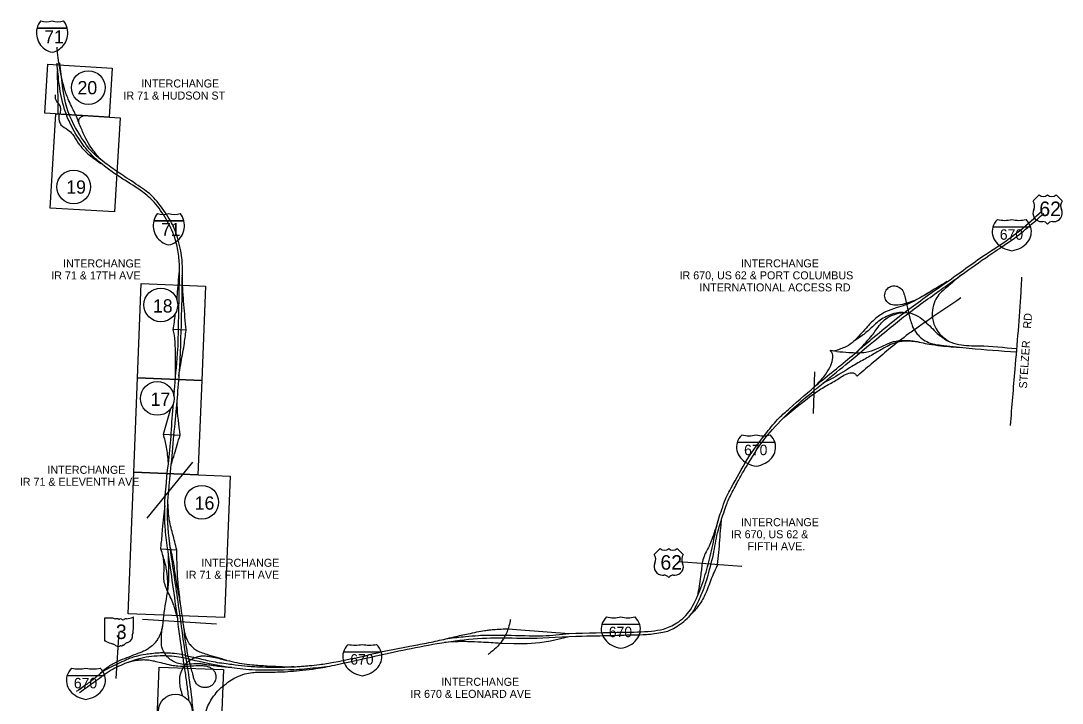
# Model space of a CAD drawing. Extents: x -13 to 322, y -402 to 112.
# Drawn here: x 3.88 to 16.74, y 73.08 to 81.51 of the extents above; entities that cross this region are included whole.
import ezdxf

# ---------------------------------------------------------------- set-up
doc = ezdxf.new("R2010")
doc.units = 0
for name, color, linetype in [('Default', 7, 'Continuous'), ('GM_X_Interstate_Shield', 7, 'Continuous'), ('GM_X_State_Shield', 7, 'Continuous'), ('GM_X_US_Shield', 7, 'Continuous'), ('SC_Scratch1', 7, 'Continuous'), ('SH_Data', 7, 'Continuous'), ('SH_Text', 7, 'Continuous')]:
    doc.layers.add(name, color=color, linetype=linetype)

# ---------------------------------------------------------------- blocks, each defined once
blk = doc.blocks.new('FENCE')
at = {"layer": 'Default'}
blk.add_lwpolyline([(-54.6, 79.5), (232.4, 79.5), (232.4, -116), (-54.6, -116)], close=True, dxfattribs=at)

msp = doc.modelspace()

# ---------------------------------------------------------------- linework, layer by layer
at = {"layer": 'GM_X_Interstate_Shield'}
for p, q in [((4.078, 81.42), (4.45, 81.42)), ((4.45, 81.42), (4.078, 81.42)), ((4.45, 81.42), (4.078, 81.42)), ((5.519, 79.04), (5.891, 79.04)), ((5.891, 79.04), (5.519, 79.04)), ((5.891, 79.04), (5.519, 79.04)), ((16.35, 78.962), (15.882, 78.962)), ((16.35, 78.962), (15.882, 78.962)), ((13.192, 76.302), (12.725, 76.302)), ((13.192, 76.302), (12.725, 76.302)), ((11.521, 74.055), (11.053, 74.055)), ((11.521, 74.055), (11.053, 74.055)), ((8.329, 73.716), (7.861, 73.716)), ((8.329, 73.716), (7.861, 73.716)), ((4.915, 73.423), (4.448, 73.423)), ((4.915, 73.423), (4.448, 73.423))]:
    msp.add_line(p, q, dxfattribs=at)
for centre, start, end in [((4.313, 81.36), 165.8066, 258.463), ((4.313, 81.36), 141.669, 165.8066), ((4.194, 81.741), 253.0091, 286.9909), ((4.335, 81.741), 253.0091, 286.9909), ((4.216, 81.36), 281.537, 14.1934), ((4.216, 81.36), 14.1934, 38.331), ((5.754, 78.981), 141.669, 165.8066), ((5.635, 79.362), 253.0091, 286.9909), ((5.776, 79.362), 253.0091, 286.9909), ((5.657, 78.981), 14.1934, 38.331), ((5.754, 78.981), 165.8066, 258.463), ((5.657, 78.981), 281.537, 14.1934)]:
    msp.add_arc(centre, 0.242, start, end, dxfattribs=at)
for centre, start_param, end_param in [((16.176, 78.907), 2.911027, 4.511031), ((16.176, 78.907), 2.47259, 2.911027), ((16.028, 79.288), 4.415841, 5.008937), ((16.204, 79.288), 4.415841, 5.008937), ((16.056, 78.907), 4.913747, 6.513751), ((16.056, 78.907), 0.230566, 0.669003), ((13.019, 76.246), 2.47259, 2.911027), ((12.87, 76.628), 4.415841, 5.008937), ((13.047, 76.628), 4.415841, 5.008937), ((12.898, 76.246), 0.230566, 0.669003), ((13.019, 76.246), 2.911027, 4.511031), ((12.898, 76.246), 4.913747, 6.513751), ((11.348, 74), 2.47259, 2.911027), ((11.199, 74.381), 4.415841, 5.008937), ((11.375, 74.381), 4.415841, 5.008937), ((11.227, 74), 0.230566, 0.669003), ((11.348, 74), 2.911027, 4.511031), ((11.227, 74), 4.913747, 6.513751), ((8.156, 73.66), 2.911027, 4.511031), ((8.156, 73.66), 2.47259, 2.911027), ((8.007, 74.042), 4.415841, 5.008937), ((8.183, 74.042), 4.415841, 5.008937), ((8.035, 73.66), 4.913747, 6.513751), ((8.035, 73.66), 0.230566, 0.669003), ((4.742, 73.368), 2.47259, 2.911027), ((4.593, 73.749), 4.415841, 5.008937), ((4.77, 73.749), 4.415841, 5.008937), ((4.621, 73.368), 0.230566, 0.669003), ((4.742, 73.368), 2.911027, 4.511031), ((4.621, 73.368), 4.913747, 6.513751)]:
    msp.add_ellipse(centre, major_axis=(0.302, 0), ratio=0.8, start_param=start_param, end_param=end_param, dxfattribs=at)
at = {"layer": 'GM_X_State_Shield'}
for p, q in [((4.911, 74.13), (4.911, 73.858)), ((5.02, 74.135), (4.915, 74.135)), ((5.27, 73.999), (5.27, 74.142)), ((5.27, 73.999), (5.27, 73.999))]:
    msp.add_line(p, q, dxfattribs=at)
for centre, radius, start, end in [((4.916, 74.131), 0.00416, 98.1301, 188.1301), ((5.045, 74.167), 0.0403, 231.6195, 271.1119), ((5.058, 73.982), 0.145, 80.4867, 94.9883), ((5.091, 74.132), 0.0116, 219.7921, 297.1024), ((5.108, 74.101), 0.0242, 54.4667, 119.1411), ((5.14, 74.144), 0.0291, 233.8562, 294.8282), ((5.191, 74.052), 0.0766, 97.3462, 120.7689), ((5.143, 74.506), 0.381, 275.8445, 288.9065), ((5.266, 74.142), 0.004, 351.8621, 97.738), ((5.285, 73.94), 0.027, 136.8065, 186.9296), ((5.269, 73.989), 0.00618, 107.944, 210.337), ((5.23, 73.971), 0.0371, 340.033, 23.6496), ((5.266, 73.999), 0.00428, 289.6038, 7.7341), ((4.916, 73.857), 0.0042, 171.9584, 258.3066), ((4.916, 73.885), 0.032, 267.339, 280.6039), ((4.923, 73.842), 0.0115, 29.7484, 93.2717), ((5.069, 74.087), 0.275, 240.4129, 257.1985), ((4.987, 73.735), 0.086, 47.1842, 75.836), ((5.204, 73.781), 0.0521, 94.4031, 142.5768), ((5.164, 73.921), 0.0952, 292.3089, 8.9858), ((5.08, 73.841), 0.0546, 230.7004, 286.2918), ((5.111, 73.747), 0.0448, 85.6951, 111.2099), ((5.115, 73.82), 0.0291, 268.777, 315.5493), ((5.141, 73.794), 0.00819, 65.7517, 132.6484), ((5.138, 73.831), 0.0308, 282.8732, 323.2771)]:
    msp.add_arc(centre, radius, start, end, dxfattribs=at)
at = {"layer": 'GM_X_US_Shield'}
for p, q in [((16.453, 79.36), (16.378, 79.286)), ((16.737, 79.286), (16.662, 79.36)), ((16.483, 79.031), (16.498, 79.031)), ((16.617, 79.031), (16.632, 79.031)), ((11.774, 74.994), (11.699, 74.92)), ((12.058, 74.92), (11.984, 74.994)), ((11.804, 74.665), (11.819, 74.665)), ((11.939, 74.665), (11.954, 74.665))]:
    msp.add_line(p, q, dxfattribs=at)
for centre, radius, start, end in [((16.505, 79.414), 0.0748, 225.573, 314.427), ((16.61, 79.414), 0.0748, 225.573, 314.427), ((16.292, 79.225), 0.105, 334.5471, 35.0009), ((16.823, 79.225), 0.105, 144.9991, 205.4529), ((16.482, 79.136), 0.105, 154.8319, 270.6383), ((16.634, 79.136), 0.105, 269.3617, 25.1681), ((16.498, 78.956), 0.0748, 36.8699, 90), ((16.617, 78.956), 0.0748, 90, 143.1301), ((11.827, 75.048), 0.0748, 225.573, 314.427), ((11.931, 75.048), 0.0748, 225.573, 314.427), ((11.614, 74.86), 0.105, 334.5471, 35.0009), ((12.144, 74.86), 0.105, 144.9991, 205.4529), ((11.803, 74.77), 0.105, 154.8319, 270.6383), ((11.955, 74.77), 0.105, 269.3617, 25.1681), ((11.819, 74.591), 0.0748, 36.8699, 90), ((11.939, 74.591), 0.0748, 90, 143.1301)]:
    msp.add_arc(centre, radius, start, end, dxfattribs=at)
at = {"layer": 'SC_Scratch1'}
for p, q in [((5.999, 76.062), (5.433, 75.368)), ((5.382, 74.122), (6.295, 74.066)), ((5.055, 73.389), (5.091, 73.967))]:
    msp.add_line(p, q, dxfattribs=at)
at = {"layer": 'SH_Data'}
for p, q in [((4.339, 80.36), (4.653, 80.341)), ((5.919, 77.69), (5.761, 77.699)), ((13.957, 77.427), (13.871, 77.438)), ((13.681, 77.177), (13.663, 76.662)), ((5.766, 76.893), (5.774, 76.937)), ((5.641, 76.408), (5.732, 76.725)), ((5.641, 76.408), (5.847, 76.394)), ((5.606, 74.989), (5.804, 74.979)), ((12.004, 74.834), (12.783, 74.776)), ((9.895, 74.001), (10.053, 73.99)), ((10.053, 73.99), (10.648, 73.945)), ((9.801, 73.827), (9.822, 73.827)), ((9.822, 73.827), (9.965, 73.82)), ((9.965, 73.82), (10.131, 73.822)), ((10.131, 73.822), (10.287, 73.833)), ((10.287, 73.833), (10.42, 73.856)), ((10.42, 73.856), (10.651, 73.91)), ((4.67, 73.303), (4.601, 73.249))]:
    msp.add_line(p, q, dxfattribs=at)
for points in [[(4.558, 80.347), (4.472, 80.523), (4.417, 80.67), (4.325, 81.186)], [(5.769, 76.876), (5.778, 76.993), (5.818, 77.462), (5.824, 77.655), (5.837, 78.418), (5.837, 78.46), (5.821, 78.654), (5.778, 78.836), (5.671, 79.063), (5.525, 79.269), (5.381, 79.398), (5.139, 79.557), (4.881, 79.739), (4.757, 79.849), (4.611, 80.031), (4.482, 80.254), (4.419, 80.415), (4.354, 80.714), (4.325, 80.987)], [(4.339, 80.36), (4.339, 80.552), (4.334, 80.714), (4.333, 80.911)], [(4.364, 80.358), (4.368, 80.45), (4.339, 80.495), (4.313, 80.53), (4.307, 80.596)], [(4.351, 80.359), (4.351, 80.275), (4.374, 80.226), (4.459, 80.165), (4.519, 80.106), (4.588, 80.001), (4.65, 79.923), (4.769, 79.819), (4.868, 79.749)], [(4.863, 79.798), (4.744, 79.949), (4.681, 80.057), (4.619, 80.194), (4.558, 80.347)], [(4.594, 80.257), (4.594, 80.286), (4.611, 80.316), (4.639, 80.335), (4.653, 80.341)], [(15.728, 78.583), (16.223, 78.927), (16.488, 79.16)], [(14.302, 77.51), (14.786, 77.906), (15.251, 78.241), (15.728, 78.583)], [(5.806, 78.066), (5.811, 78.127), (5.837, 78.425)], [(5.919, 77.69), (5.905, 77.849), (5.88, 78.165), (5.872, 78.371)], [(15.493, 78.372), (15.316, 78.223), (15.19, 78.094), (15.148, 78), (15.134, 77.87), (15.144, 77.801), (15.17, 77.731), (15.229, 77.643), (15.34, 77.551)], [(16.237, 78.344), (16.227, 78.159), (16.153, 77.209), (16.096, 76.515)], [(15.319, 78.291), (15.063, 78.137), (14.945, 78.071), (14.792, 78.016), (14.68, 78), (14.605, 78.017), (14.564, 78.057), (14.546, 78.113), (14.566, 78.185), (14.607, 78.223), (14.659, 78.238), (14.714, 78.227), (14.77, 78.175), (14.794, 78.105), (14.863, 77.82), (14.886, 77.748), (14.907, 77.7), (14.922, 77.68), (14.958, 77.631), (15.025, 77.573), (15.108, 77.531), (15.163, 77.516), (15.272, 77.502), (15.591, 77.469), (16.171, 77.423)], [(15.078, 78.146), (14.804, 78.003), (14.687, 77.965), (14.557, 77.915), (14.438, 77.838), (14.336, 77.737), (14.26, 77.655), (14.099, 77.503), (13.968, 77.446)], [(15.488, 78.088), (15.093, 77.82), (14.975, 77.738), (14.842, 77.644), (14.618, 77.471), (14.426, 77.309)], [(5.761, 77.697), (5.786, 77.883), (5.788, 77.899)], [(14.775, 77.908), (14.688, 77.902), (14.569, 77.858), (14.49, 77.813), (14.381, 77.72), (14.273, 77.628), (14.173, 77.557)], [(14.211, 77.431), (14.321, 77.546), (14.393, 77.628), (14.437, 77.689), (14.493, 77.766), (14.546, 77.82), (14.607, 77.861), (14.703, 77.896), (14.765, 77.907), (14.871, 77.899), (14.984, 77.845), (15.139, 77.705), (15.216, 77.632), (15.33, 77.556), (15.462, 77.513), (15.715, 77.497), (16.175, 77.463)], [(5.787, 77.091), (5.787, 77.294), (5.774, 77.627), (5.761, 77.697)], [(5.828, 77.122), (5.852, 77.268), (5.894, 77.504), (5.919, 77.69)], [(13.957, 77.427), (14.105, 77.416), (14.315, 77.42), (14.447, 77.46), (14.591, 77.526), (14.72, 77.561), (14.763, 77.562), (14.893, 77.559), (14.998, 77.538), (15.094, 77.519), (15.24, 77.498), (15.498, 77.477)], [(14.972, 77.543), (14.793, 77.553), (14.664, 77.53), (14.575, 77.49), (14.437, 77.411), (14.291, 77.328), (14.141, 77.242)], [(10.648, 73.945), (11.322, 73.961), (11.666, 73.975), (11.813, 74), (11.978, 74.075), (12.071, 74.146), (12.206, 74.345), (12.311, 74.609), (12.383, 74.863), (12.445, 75.142), (12.499, 75.37), (12.535, 75.475), (12.582, 75.605), (12.651, 75.743), (12.85, 76.094), (13.089, 76.427), (13.245, 76.608), (13.368, 76.721), (13.727, 77.032), (14.172, 77.398), (14.302, 77.51)], [(13.705, 77.014), (13.82, 77.149), (13.882, 77.256), (13.906, 77.351), (13.893, 77.413), (13.871, 77.438)], [(13.974, 77.447), (13.888, 77.434), (13.871, 77.438)], [(14.428, 77.31), (14.241, 77.153), (14.207, 77.124)], [(13.27, 76.582), (13.671, 76.905), (13.814, 76.998), (13.956, 77.078), (14.103, 77.159), (14.173, 77.156), (14.198, 77.133), (14.207, 77.124)], [(14.141, 77.242), (13.913, 77.104), (13.784, 77.035)], [(5.815, 74.129), (5.696, 74.964), (5.663, 75.231), (5.655, 75.417), (5.7, 76.039), (5.733, 76.381), (5.735, 76.416), (5.763, 76.787)], [(5.847, 76.394), (5.809, 76.768), (5.807, 76.836)], [(5.701, 76.049), (5.691, 76.154), (5.676, 76.244), (5.641, 76.408)], [(5.737, 76.039), (5.776, 76.162), (5.807, 76.275), (5.847, 76.394)], [(5.606, 74.989), (5.613, 75.055), (5.629, 75.229), (5.643, 75.388), (5.661, 75.522)], [(5.804, 74.979), (5.753, 75.178), (5.708, 75.375), (5.698, 75.543)], [(12.496, 75.36), (12.421, 75.13), (12.387, 75.042), (12.315, 74.897), (12.292, 74.813)], [(12.483, 74.799), (12.498, 74.947), (12.523, 75.252), (12.533, 75.359)], [(5.21, 73.592), (5.292, 73.612), (5.337, 73.619), (5.396, 73.622), (5.457, 73.618), (5.523, 73.606), (5.609, 73.585), (5.705, 73.562), (5.743, 73.554), (5.817, 73.544), (5.947, 73.543), (5.983, 73.545), (6.099, 73.549), (6.151, 73.546), (6.195, 73.535), (6.23, 73.518), (6.263, 73.485), (6.28, 73.454), (6.287, 73.407), (6.281, 73.374), (6.27, 73.347), (6.246, 73.313), (6.204, 73.287), (6.163, 73.277), (6.118, 73.281), (6.085, 73.294), (6.049, 73.324), (6.034, 73.347), (6.02, 73.378), (6.006, 73.427), (5.987, 73.5), (5.969, 73.566), (5.958, 73.611), (5.946, 73.663), (5.918, 73.819), (5.886, 74.056), (5.877, 74.127), (5.836, 74.389), (5.809, 74.535), (5.792, 74.64), (5.762, 74.832), (5.716, 75.053)], [(5.813, 74.14), (5.78, 74.252), (5.761, 74.313), (5.744, 74.356), (5.702, 74.442), (5.676, 74.5), (5.662, 74.537), (5.65, 74.576), (5.646, 74.614), (5.646, 74.692), (5.648, 74.783), (5.642, 74.859), (5.635, 74.899), (5.606, 74.989)], [(5.849, 74.316), (5.837, 74.422), (5.822, 74.559), (5.81, 74.735), (5.804, 74.979)], [(6.483, 73.524), (6.313, 73.539), (6.234, 73.55), (6.152, 73.562), (6.106, 73.569), (6.04, 73.571), (5.942, 73.564), (5.885, 73.564), (5.808, 73.579), (5.739, 73.614), (5.717, 73.63), (5.677, 73.669), (5.651, 73.705), (5.615, 73.801), (5.615, 73.834), (5.615, 73.917), (5.637, 74.092), (5.64, 74.122), (5.689, 74.451), (5.701, 74.541), (5.706, 74.619), (5.706, 74.716), (5.701, 74.926)], [(5.692, 74.472), (5.692, 74.554), (5.692, 74.586), (5.689, 74.634), (5.682, 74.705), (5.671, 74.768), (5.657, 74.828), (5.633, 74.903)], [(12.485, 74.799), (12.405, 74.621), (12.327, 74.423), (12.239, 74.277), (12.122, 74.147)], [(12.292, 74.813), (12.272, 74.647), (12.235, 74.41)], [(5.955, 73.11), (5.951, 73.153), (5.94, 73.241), (5.929, 73.328), (5.904, 73.503), (5.879, 73.662), (5.867, 73.741), (5.855, 73.821), (5.823, 74.059), (5.815, 74.129)], [(9.924, 74.119), (9.922, 74.102), (9.9, 74.017), (9.879, 73.957), (9.821, 73.857), (9.769, 73.79), (9.684, 73.713), (9.649, 73.687)], [(5.628, 74.034), (5.602, 73.945), (5.572, 73.882), (5.543, 73.84), (5.513, 73.806), (5.459, 73.762), (5.418, 73.737), (5.323, 73.697), (5.101, 73.612)], [(5.894, 73.995), (5.909, 73.925), (5.921, 73.891), (5.941, 73.847), (5.959, 73.819), (5.995, 73.779), (6.038, 73.743), (6.099, 73.714), (6.175, 73.688), (6.297, 73.653), (6.418, 73.615)], [(9.113, 73.875), (9.23, 73.904), (9.403, 73.941), (9.51, 73.964), (9.608, 73.982), (9.663, 73.989), (9.736, 73.996), (9.836, 74.001), (9.895, 74.001)], [(7.742, 73.59), (8.185, 73.684), (8.218, 73.692), (8.726, 73.797), (8.944, 73.838), (9.153, 73.882), (9.369, 73.908), (9.53, 73.921), (9.632, 73.926), (9.847, 73.924), (9.876, 73.924), (10.326, 73.918), (10.648, 73.945)], [(9.112, 73.84), (9.278, 73.848), (9.394, 73.848), (9.564, 73.841), (9.801, 73.827)], [(7.248, 73.533), (7.027, 73.524), (6.863, 73.528), (6.677, 73.539), (6.526, 73.555), (6.439, 73.566), (6.228, 73.599), (6.043, 73.641), (6.004, 73.649), (5.863, 73.684), (5.747, 73.7), (5.662, 73.704), (5.586, 73.704), (5.491, 73.696), (5.421, 73.687), (5.301, 73.661), (5.232, 73.64), (5.173, 73.617)], [(5.188, 73.584), (4.993, 73.491), (4.802, 73.356), (4.601, 73.212)], [(5.101, 73.612), (4.974, 73.544), (4.829, 73.423)], [(5.875, 73.176), (5.874, 73.183), (5.868, 73.206), (5.862, 73.228), (5.855, 73.25), (5.85, 73.272), (5.846, 73.3), (5.841, 73.352), (5.843, 73.415), (5.854, 73.454), (5.875, 73.505), (5.915, 73.569), (5.97, 73.619), (5.991, 73.63), (6.012, 73.64), (6.055, 73.656), (6.085, 73.664), (6.129, 73.669), (6.19, 73.665), (6.278, 73.648), (6.36, 73.629), (6.485, 73.598), (6.606, 73.575), (6.735, 73.56), (6.919, 73.545), (7.065, 73.538), (7.229, 73.532), (7.314, 73.538), (7.377, 73.543), (7.44, 73.548), (7.565, 73.562), (7.742, 73.59)], [(4.998, 72.246), (5.148, 72.205), (5.252, 72.181), (5.432, 72.14), (5.523, 72.119), (5.603, 72.112), (5.686, 72.115), (5.736, 72.125), (5.778, 72.136), (5.859, 72.176), (5.897, 72.204), (5.946, 72.246), (5.993, 72.299), (6.048, 72.399), (6.094, 72.525), (6.111, 72.642), (6.125, 72.809), (6.138, 72.886), (6.17, 73.003), (6.211, 73.095), (6.276, 73.193), (6.343, 73.268), (6.365, 73.286), (6.461, 73.362), (6.542, 73.406), (6.644, 73.445), (6.739, 73.462), (6.812, 73.468), (6.965, 73.468), (7.073, 73.471), (7.21, 73.478), (7.357, 73.494), (7.522, 73.511), (7.75, 73.556)], [(7.25, 73.497), (7.383, 73.509), (7.658, 73.538)]]:
    msp.add_spline(points, degree=3, dxfattribs=at)
for points in [[(5.849, 74.134), (5.806, 74.442), (5.758, 74.75), (5.673, 75.362), (5.703, 75.666), (5.787, 76.592), (5.846, 77.213), (5.867, 77.986), (5.872, 78.141), (5.873, 78.454), (5.873, 78.615), (5.79, 78.923), (5.718, 79.067), (5.533, 79.329), (5.401, 79.428), (5.143, 79.6), (5.009, 79.685), (4.772, 79.866), (4.676, 79.988), (4.433, 80.375), (4.393, 80.682), (4.36, 80.991)], [(15.748, 78.554), (15.877, 78.644), (16.014, 78.728), (16.274, 78.917), (16.392, 79.029), (16.511, 79.133)], [(14.325, 77.483), (14.556, 77.672), (14.78, 77.864), (15.264, 78.207), (15.507, 78.381), (15.748, 78.554)], [(10.649, 73.91), (10.883, 73.915), (11.117, 73.919), (11.469, 73.931), (11.582, 73.929), (11.829, 73.957), (11.943, 74.002), (12.148, 74.152), (12.212, 74.266), (12.311, 74.484), (12.346, 74.599), (12.442, 74.939), (12.469, 75.175), (12.581, 75.501), (12.618, 75.609), (12.73, 75.815), (12.785, 75.918), (12.963, 76.216), (13.103, 76.409), (13.418, 76.736), (13.605, 76.885), (13.963, 77.185), (14.147, 77.33), (14.325, 77.483)], [(6.008, 72.952), (6, 73.071), (5.986, 73.19), (5.933, 73.585), (5.882, 73.859), (5.85, 74.134)], [(7.75, 73.556), (8.229, 73.657), (8.716, 73.776), (9.658, 73.93), (10.163, 73.869), (10.651, 73.91)], [(5.173, 73.616), (5.104, 73.583), (5.039, 73.554), (4.893, 73.479), (4.834, 73.426), (4.708, 73.326), (4.635, 73.279), (4.563, 73.229)], [(7.25, 73.497), (6.889, 73.484), (6.512, 73.5), (5.971, 73.62), (5.796, 73.671), (5.474, 73.67), (5.33, 73.633), (5.188, 73.584)]]:
    msp.add_open_spline(points, degree=3, dxfattribs=at)
at = {"layer": 'SH_Text'}
for p, q in [((4.213, 80.974), (5.005, 80.925)), ((5.319, 77.1), (5.366, 78.265)), ((5.366, 78.265), (6.159, 78.233)), ((6.159, 78.233), (6.113, 77.068)), ((5.272, 75.936), (5.319, 77.1)), ((5.319, 77.1), (6.113, 77.068)), ((6.113, 77.068), (5.319, 77.1)), ((6.113, 77.068), (6.066, 75.904)), ((5.202, 74.189), (5.272, 75.936)), ((6.066, 75.904), (5.272, 75.936)), ((5.272, 75.936), (6.463, 75.888)), ((6.463, 75.888), (6.393, 74.141)), ((6.393, 74.141), (5.202, 74.189)), ((5.539, 72.366), (5.586, 73.53)), ((5.586, 73.53), (6.379, 73.499)), ((6.379, 73.499), (6.332, 72.334))]:
    msp.add_line(p, q, dxfattribs=at)
msp.add_lwpolyline([(5.005, 80.925), (4.968, 80.322), (4.176, 80.37), (4.213, 80.974)], dxfattribs=at)
for centre in [(4.711, 80.686), (4.531, 79.46), (5.607, 78.003), (5.563, 76.847), (6.113, 75.566), (5.787, 72.988)]:
    msp.add_circle(centre, 0.208, dxfattribs=at)

# ---------------------------------------------------------------- block references
at = {"layer": 'SH_Text', "xscale": 0.00406045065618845, "yscale": 0.00406045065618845, "rotation": 86.51601125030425}
msp.add_blockref('FENCE', (4.577, 79.4), dxfattribs=at)

# ---------------------------------------------------------------- texts
at = {"layer": 'GM_X_Interstate_Shield'}
for s, height, p in [('71', 0.1611, (4.168, 81.232)), ('71', 0.1611, (5.61, 78.853)), ('670', 0.1289, (15.968, 78.807)), ('670', 0.1289, (12.81, 76.147)), ('670', 0.1289, (11.139, 73.9)), ('670', 0.1289, (7.947, 73.561)), ('670', 0.1289, (4.533, 73.268))]:
    msp.add_text(s, height=height, dxfattribs=at).set_placement(p)
at = {"layer": 'GM_X_State_Shield'}
msp.add_text('3', height=0.179, dxfattribs=at).set_placement((5.052, 73.877))
at = {"layer": 'GM_X_US_Shield'}
for p in [(16.456, 79.099), (11.777, 74.733)]:
    msp.add_text('62', height=0.1795, dxfattribs=at).set_placement(p)
at = {"layer": 'SH_Text'}
for s, height, p in [('20', 0.1636, (4.578, 80.603)), ('INTERCHANGE', 0.09886, (5.365, 80.687)), ('IR 71 & HUDSON ST', 0.09886, (5.145, 80.538)), ('19', 0.1636, (4.439, 79.376)), ('INTERCHANGE', 0.09886, (4.4, 78.465)), ('INTERCHANGE', 0.09886, (12.771, 78.466)), ('IR 71 & 17TH AVE', 0.09886, (4.254, 78.317)), ('IR 670, US 62 & PORT COLUMBUS', 0.09886, (12.013, 78.318)), ('INTERNATIONAL ACCESS RD', 0.09886, (12.259, 78.169)), ('18', 0.1636, (5.509, 77.908)), ('17', 0.1636, (5.48, 76.756)), ('INTERCHANGE', 0.09886, (4.207, 75.917)), ('IR 71 & ELEVENTH AVE', 0.09886, (3.866, 75.769)), ('16', 0.1636, (6.025, 75.474)), ('INTERCHANGE', 0.09886, (12.771, 75.27)), ('IR 670, US 62 &', 0.09886, (12.648, 75.121)), ('FIFTH AVE.', 0.0989, (12.853, 74.973)), ('INTERCHANGE', 0.09886, (6.108, 74.769)), ('IR 71 & FIFTH AVE', 0.09886, (5.915, 74.621)), ('INTERCHANGE', 0.09886, (9.07, 73.299)), ('IR 670 & LEONARD AVE', 0.09886, (8.689, 73.15))]:
    msp.add_text(s, height=height, dxfattribs=at).set_placement(p)
msp.add_text('STELZER    RD', height=0.09886, rotation=86.0247, dxfattribs=at).set_placement((16.302, 76.967))

doc.saveas('drawing.dxf')
